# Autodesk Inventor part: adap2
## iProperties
Created: 2006-11
Part Number: adap2
Material: Default
Document SubType Name: Modeling
Designer: WINDGES
Manufacturer: Standard
Standards Organization: Custom
Author: WINDGES
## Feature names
1. Extrusion1
2. Extrusion2
